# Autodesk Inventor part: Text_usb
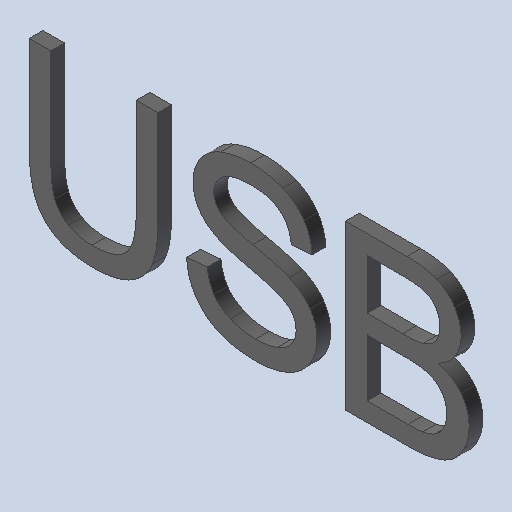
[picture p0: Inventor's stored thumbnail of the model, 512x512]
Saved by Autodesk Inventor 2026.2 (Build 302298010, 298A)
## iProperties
Created: 2026-10
Part Number: Text_usb
Material: Générique
Document SubType Name: Modeling
Designer: mel
Density: 1 g/cm^3
Appearance: Par défaut
Author: mel
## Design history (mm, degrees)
feature "Base1"
feature "Base2"
feature "Base3"
node "Solide1"
node "Solide2"
node "Solide3"
